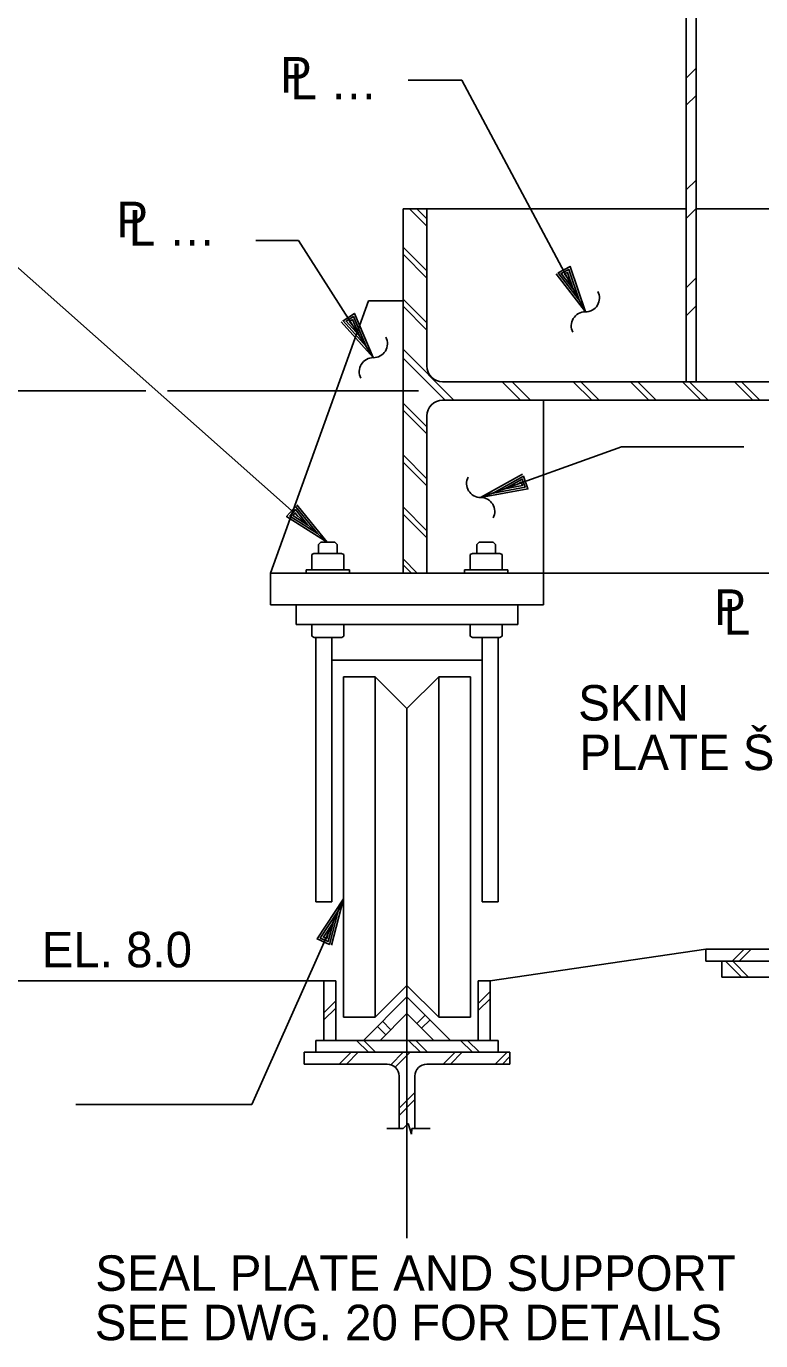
# Model space of a CAD drawing. Extents: x 4.9 to 31.6, y 3.9 to 22.6.
# Drawn here: x 24.231 to 26.163, y 14.546 to 18.004 of the extents above; entities that cross this region are included whole.
import ezdxf

# ---------------------------------------------------------------- set-up
doc = ezdxf.new("R2010")
doc.units = 0
for name, color, linetype in [('Level 2', 7, 'Continuous'), ('Level 25', 7, 'Continuous'), ('Level 3', 7, 'Continuous'), ('Level 44', 7, 'Continuous'), ('Level 50', 7, 'Continuous')]:
    doc.layers.add(name, color=color, linetype=linetype)

msp = doc.modelspace()

# ---------------------------------------------------------------- linework, layer by layer
at = {"layer": 'Level 2'}
for p, q in [((25.9666, 17.0688), (25.9666, 20.753)), ((25.9927, 17.0688), (25.9927, 20.6801)), ((25.2218, 17.5238), (25.2843, 17.5238)), ((25.2218, 16.5655), (25.2218, 17.5238)), ((25.2843, 17.4784), (25.2388, 17.5238)), ((25.2843, 17.4972), (25.2577, 17.5238)), ((25.2843, 17.1105), (25.2843, 17.5238)), ((25.9666, 17.5238), (25.2843, 17.5238)), ((27.8885, 17.5238), (25.9927, 17.5238)), ((25.2843, 17.3605), (25.2218, 17.423)), ((25.2843, 17.3416), (25.2218, 17.4041)), ((25.1311, 17.2819), (24.8729, 16.5655)), ((25.1311, 17.2819), (25.2218, 17.2819)), ((25.2843, 17.2238), (25.2218, 17.2863)), ((25.2843, 17.2049), (25.2218, 17.2674)), ((25.3558, 17.0205), (25.2218, 17.1545)), ((25.3323, 17.0203), (25.2218, 17.1307)), ((25.326, 17.0688), (26.4145, 17.0688)), ((25.5306, 17.0205), (25.4823, 17.0688)), ((25.5574, 17.0205), (25.5091, 17.0688)), ((25.718, 17.0205), (25.6696, 17.0688)), ((25.7358, 17.0218), (25.6874, 17.0701)), ((25.8685, 17.0205), (25.8201, 17.0688)), ((25.8873, 17.0205), (25.839, 17.0688)), ((26.0052, 17.0205), (25.9568, 17.0688)), ((26.024, 17.0205), (25.9757, 17.0688)), ((26.1419, 17.0205), (26.0936, 17.0688)), ((26.1607, 17.0205), (26.1124, 17.0688)), ((25.2843, 16.9504), (25.2218, 17.0129)), ((25.326, 17.0205), (26.4145, 17.0205)), ((25.2843, 16.9315), (25.2218, 16.994)), ((25.2843, 16.5655), (25.2843, 16.9788)), ((25.2843, 16.8137), (25.2218, 16.8762)), ((25.2843, 16.7948), (25.2218, 16.8573)), ((25.2843, 16.677), (25.2218, 16.7395)), ((25.2843, 16.6581), (25.2218, 16.7206)), ((24.9997, 16.6406), (25.0057, 16.6467)), ((24.9997, 16.6406), (24.9997, 16.6172)), ((25.0057, 16.6467), (25.0421, 16.6467)), ((25.0482, 16.6406), (25.0421, 16.6467)), ((25.0482, 16.6406), (25.0482, 16.6172)), ((25.4163, 16.6406), (25.4224, 16.6467)), ((25.4163, 16.6406), (25.4163, 16.6172)), ((25.4587, 16.6467), (25.4224, 16.6467)), ((25.4648, 16.6406), (25.4587, 16.6467)), ((25.4648, 16.6406), (25.4648, 16.6172)), ((24.9876, 16.6172), (24.982, 16.614)), ((24.982, 16.5742), (24.982, 16.614)), ((24.9876, 16.6172), (25.0602, 16.6172)), ((25.0602, 16.6172), (25.0657, 16.614)), ((25.0657, 16.5742), (25.0657, 16.614)), ((25.2592, 16.5655), (25.2218, 16.6029)), ((25.4043, 16.6172), (25.3987, 16.614)), ((25.3987, 16.5742), (25.3987, 16.614)), ((25.4768, 16.6172), (25.4043, 16.6172)), ((25.4768, 16.6172), (25.4824, 16.614)), ((25.4824, 16.5742), (25.4824, 16.614)), ((24.8729, 16.5655), (26.4145, 16.5655)), ((24.9672, 16.5742), (25.0806, 16.5742)), ((24.9672, 16.5655), (24.9672, 16.5742)), ((24.982, 16.5742), (25.0657, 16.5742)), ((25.0032, 16.5742), (24.982, 16.5742)), ((24.9997, 16.5727), (24.9997, 16.5742)), ((25.0482, 16.5727), (25.0482, 16.5742)), ((25.0806, 16.5655), (25.0806, 16.5742)), ((25.2437, 16.5655), (25.2218, 16.5874)), ((25.4972, 16.5742), (25.3839, 16.5742)), ((25.3839, 16.5655), (25.3839, 16.5742)), ((25.4824, 16.5742), (25.3987, 16.5742)), ((25.4163, 16.5727), (25.4163, 16.5742)), ((25.4612, 16.5742), (25.4824, 16.5742)), ((25.4648, 16.5727), (25.4648, 16.5742)), ((25.4972, 16.5655), (25.4972, 16.5742)), ((24.9406, 16.4301), (24.9406, 16.4821)), ((25.5239, 16.4301), (25.5239, 16.4821)), ((24.9406, 16.4301), (25.2322, 16.4301)), ((24.9823, 16.4299), (25.066, 16.4299)), ((25.0034, 16.4299), (24.9823, 16.4299)), ((24.9823, 16.4299), (24.9823, 16.3992)), ((24.9999, 16.4314), (24.9999, 16.4299)), ((25.0484, 16.4314), (25.0484, 16.4299)), ((25.066, 16.4299), (25.066, 16.3992)), ((25.5239, 16.4301), (25.2322, 16.4301)), ((25.4822, 16.4299), (25.3984, 16.4299)), ((25.3984, 16.4299), (25.3984, 16.3992)), ((25.4161, 16.4314), (25.4161, 16.4299)), ((25.461, 16.4299), (25.4822, 16.4299)), ((25.4646, 16.4314), (25.4646, 16.4299)), ((25.4822, 16.4299), (25.4822, 16.3992)), ((24.9879, 16.396), (24.9823, 16.3992)), ((24.9879, 16.396), (25.0604, 16.396)), ((24.9927, 15.7009), (24.9927, 16.396)), ((25.0343, 15.7009), (25.0343, 16.396)), ((25.0604, 16.396), (25.066, 16.3992)), ((25.4041, 16.396), (25.3984, 16.3992)), ((25.4766, 16.396), (25.4041, 16.396)), ((25.4302, 15.7009), (25.4302, 16.396)), ((25.4718, 15.7009), (25.4718, 16.396)), ((25.4766, 16.396), (25.4822, 16.3992)), ((25.0343, 16.3363), (25.2322, 16.3363)), ((25.4302, 16.3363), (25.2322, 16.3363)), ((25.1489, 16.2929), (25.0656, 16.2929)), ((25.0656, 15.397), (25.0656, 16.2929)), ((25.1489, 15.397), (25.1489, 16.2929)), ((25.1489, 16.2929), (25.2322, 16.2095)), ((25.3156, 16.2929), (25.2322, 16.2095)), ((25.3156, 15.397), (25.3156, 16.2929)), ((25.3156, 16.2929), (25.3989, 16.2929)), ((25.3989, 15.397), (25.3989, 16.2929)), ((25.2322, 15.4804), (25.2322, 16.2095)), ((24.9927, 15.7009), (25.0343, 15.7009)), ((25.4718, 15.7009), (25.4302, 15.7009)), ((26.0187, 15.5759), (25.451, 15.4926)), ((26.0187, 15.5759), (26.0187, 15.5446)), ((26.0187, 15.5759), (26.3937, 15.5759)), ((26.0875, 15.5446), (26.1187, 15.5759)), ((26.1063, 15.5446), (26.1376, 15.5759)), ((26.0187, 15.5446), (26.3937, 15.5446)), ((26.0604, 15.503), (26.0604, 15.5446)), ((26.1118, 15.503), (26.0701, 15.5446)), ((26.1307, 15.503), (26.089, 15.5446)), ((22.4339, 15.4926), (25.0135, 15.4926)), ((25.0135, 15.4926), (25.0135, 15.3363)), ((25.0135, 15.4926), (25.0447, 15.4926)), ((25.0447, 15.4926), (25.0447, 15.3363)), ((25.4197, 15.4926), (25.4197, 15.3363)), ((25.451, 15.4926), (25.4197, 15.4926)), ((25.451, 15.4926), (25.451, 15.3363)), ((26.3312, 15.503), (26.0604, 15.503)), ((25.2322, 15.4804), (25.1489, 15.397)), ((25.2322, 15.4804), (25.3156, 15.397)), ((25.4197, 15.4335), (25.451, 15.4647)), ((25.0135, 15.4089), (25.0447, 15.4401)), ((25.0135, 15.39), (25.0447, 15.4212)), ((25.2322, 15.4509), (25.1177, 15.3363)), ((25.2322, 15.4509), (25.3468, 15.3363)), ((25.4197, 15.4146), (25.451, 15.4459)), ((25.1489, 15.397), (25.0656, 15.397)), ((25.2322, 15.4067), (25.1618, 15.3363)), ((25.19, 15.3645), (25.1679, 15.3866)), ((25.2322, 15.4067), (25.3026, 15.3363)), ((25.2582, 15.3808), (25.2803, 15.4029)), ((25.2708, 15.3681), (25.2929, 15.3902)), ((25.3156, 15.397), (25.3989, 15.397)), ((25.1765, 15.351), (25.1544, 15.3731)), ((25.2322, 15.3363), (24.9927, 15.3363)), ((24.9927, 15.3363), (24.9927, 15.3051)), ((25.1308, 15.3051), (25.0995, 15.3363)), ((25.1496, 15.3051), (25.1184, 15.3363)), ((25.2322, 15.3363), (25.4718, 15.3363)), ((25.2675, 15.3051), (25.2362, 15.3363)), ((25.2863, 15.3051), (25.2551, 15.3363)), ((25.4042, 15.3051), (25.3729, 15.3363)), ((25.423, 15.3051), (25.3918, 15.3363)), ((25.4718, 15.3363), (25.4718, 15.3051)), ((25.2322, 15.3051), (24.9614, 15.3051)), ((24.9614, 15.2738), (24.9614, 15.3051)), ((25.0541, 15.2738), (25.0853, 15.3051)), ((25.0729, 15.2738), (25.1042, 15.3051)), ((25.1894, 15.2724), (25.222, 15.3051)), ((25.2013, 15.2655), (25.2409, 15.3051)), ((25.2322, 15.3051), (25.5031, 15.3051)), ((25.3275, 15.2738), (25.3587, 15.3051)), ((25.3463, 15.2738), (25.3776, 15.3051)), ((25.4642, 15.2738), (25.4954, 15.3051)), ((25.483, 15.2738), (25.5031, 15.2939)), ((25.5031, 15.2738), (25.5031, 15.3051)), ((25.1802, 15.2738), (24.9614, 15.2738)), ((25.2843, 15.2738), (25.5031, 15.2738)), ((25.2114, 15.2426), (25.2114, 15.1044)), ((25.2531, 15.2426), (25.2531, 15.1044)), ((25.2114, 15.1577), (25.2531, 15.1994)), ((25.2114, 15.1389), (25.2531, 15.1806))]:
    msp.add_line(p, q, dxfattribs=at)
for centre, radius, start, end in [((25.326, 17.1105), 0.0417, 180, 270), ((25.326, 16.9788), 0.0417, 90, 180), ((25.1801, 15.2426), 0.0313, 0, 90), ((25.2843, 15.2426), 0.0313, 90, 180)]:
    msp.add_arc(centre, radius, start, end, dxfattribs=at)
at = {"layer": 'Level 3'}
for points in [[(25.2357, 17.8622), (25.3769, 17.8622)], [(25.3769, 17.8622), (25.7014, 17.2526)], [(23.9823, 17.5693), (25.0223, 16.6467)], [(24.8344, 17.4405), (24.947, 17.4405)], [(24.947, 17.4405), (25.1436, 17.1322)], [(26.1184, 16.8975), (25.7968, 16.8975), (25.426, 16.7643)], [(24.8243, 15.1676), (25.0656, 15.7086)]]:
    msp.add_lwpolyline(points, dxfattribs=at)
at = {"layer": 'Level 44'}
for p, q in [((25.9666, 17.8678), (25.9927, 17.8939)), ((25.9666, 17.796), (25.9927, 17.822)), ((25.9666, 17.5732), (25.9927, 17.5993)), ((25.9666, 17.4985), (25.9927, 17.5245)), ((25.9666, 17.3158), (25.9927, 17.3418)), ((25.9666, 17.2424), (25.9927, 17.2684)), ((25.222, 15.1044), (25.2354, 15.1176)), ((25.2354, 15.1176), (25.244, 15.0894)), ((25.244, 15.0894), (25.2452, 15.1044))]:
    msp.add_line(p, q, dxfattribs=at)
for centre, start, end in [((25.7017, 17.2893), 269.5981, 27.4773), ((25.7011, 17.2158), 89.5981, 207.4773), ((25.1439, 17.1689), 269.5981, 27.4773), ((25.1434, 17.0954), 89.5981, 207.4773), ((25.4257, 16.8011), 152.5227, 270.4019), ((25.4262, 16.7275), 332.5227, 90.4019)]:
    msp.add_arc(centre, 0.0368, start, end, dxfattribs=at)
at = {"layer": 'Level 50'}
for p, q in [((25.6851, 17.2832), (25.6851, 17.2832)), ((25.7014, 17.2526), (25.7014, 17.2526)), ((25.125, 17.1614), (25.125, 17.1614)), ((25.1436, 17.1322), (25.1436, 17.1322)), ((24.5451, 17.0446), (24.0732, 17.0446)), ((25.2625, 17.0446), (24.6027, 17.0446)), ((25.5916, 16.4821), (25.5916, 17.0205)), ((25.4586, 16.776), (25.4586, 16.776)), ((25.426, 16.7643), (25.426, 16.7643)), ((24.9964, 16.6697), (24.9964, 16.6697)), ((25.0223, 16.6467), (25.0223, 16.6467)), ((24.8729, 16.4821), (24.8729, 16.5655)), ((25.5916, 16.4821), (24.8729, 16.4821)), ((25.0656, 15.7086), (25.0656, 15.7086)), ((25.0515, 15.677), (25.0515, 15.677)), ((25.2322, 15.4804), (25.2322, 14.8162)), ((24.8243, 15.1676), (24.3611, 15.1676)), ((25.1794, 15.1044), (25.222, 15.1044)), ((25.2452, 15.1044), (25.2928, 15.1044))]:
    msp.add_line(p, q, dxfattribs=at)
for points in [[(25.6246, 17.3529), (25.7014, 17.2526), (25.6611, 17.3723), (25.6299, 17.3557), (25.6851, 17.2832), (25.6577, 17.3645), (25.6377, 17.3538), (25.6695, 17.3126), (25.6543, 17.3566), (25.6461, 17.3523), (25.6532, 17.3432)], [(25.0592, 17.2262), (25.1436, 17.1322), (25.094, 17.2484), (25.0642, 17.2294), (25.125, 17.1614), (25.0913, 17.2403), (25.0722, 17.2281), (25.1071, 17.1895), (25.0885, 17.2322), (25.0806, 17.2272), (25.0884, 17.2187)], [(25.5363, 16.8259), (25.426, 16.7643), (25.5503, 16.787), (25.5383, 16.8203), (25.4586, 16.776), (25.543, 16.7915), (25.5353, 16.8128), (25.49, 16.7873), (25.5357, 16.7959), (25.5326, 16.8047), (25.5226, 16.799)], [(24.9428, 16.7449), (25.0223, 16.6467), (24.9153, 16.714), (24.9388, 16.7404), (24.9964, 16.6697), (24.9238, 16.7154), (24.9388, 16.7324), (24.9714, 16.6918), (24.9322, 16.7169), (24.9384, 16.7239), (24.9455, 16.7148)], [(25.0337, 15.5864), (25.0656, 15.7086), (24.9959, 15.6032), (25.0282, 15.5888), (25.0515, 15.677), (25.0042, 15.6054), (25.0249, 15.5961), (25.0379, 15.6465), (25.0124, 15.6075), (25.021, 15.6037), (25.0238, 15.6149)]]:
    msp.add_lwpolyline(points, dxfattribs=at)

# ---------------------------------------------------------------- texts
at = {"layer": 'Level 25'}
for s, height, p in [('P', 0.0933, (24.8986, 17.8296)), ('L …', 0.09329, (24.9257, 17.8121)), ('P', 0.0933, (24.4679, 17.4491)), ('L …', 0.09329, (24.5007, 17.4269)), ('P', 0.0933, (26.0402, 16.4292)), ('L …X4', 0.09329, (26.0654, 16.4038)), ('SKIN ', 0.09329, (25.6825, 16.1777)), ('PLATE Š', 0.09329, (25.6856, 16.0473)), (' EL. 8.0', 0.09329, (24.2368, 15.5285)), ('SEAL PLATE AND SUPPORT', 0.093292, (24.4124, 14.6776)), ('SEE DWG. 20 FOR DETAILS', 0.093292, (24.4109, 14.5477))]:
    msp.add_text(s, height=height, dxfattribs=at).set_placement(p)

doc.saveas('drawing.dxf')
